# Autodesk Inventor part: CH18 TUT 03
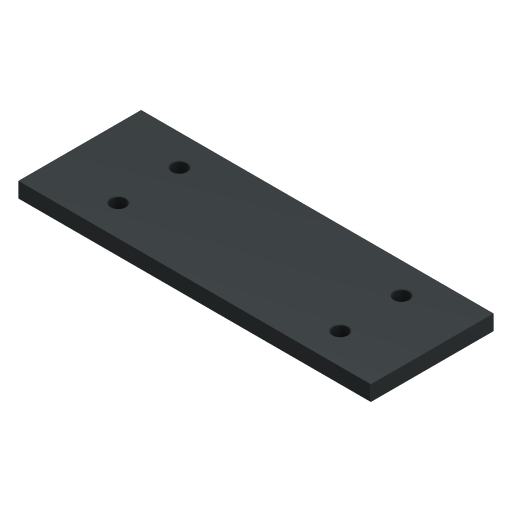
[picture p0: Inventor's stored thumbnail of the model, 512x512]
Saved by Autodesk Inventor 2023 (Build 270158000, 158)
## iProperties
Created: 2016-05
Part Number: CH18 TUT 03
Material: Iron, Cast
Document SubType Name: Modeling
Designer: CADCIM
Density: 7.15 g/cm^3
Appearance: Iron Gray
Mass: 161.642 g
Surface Area: 109.071 cm^2
Volume: 22.6073 cm^3
Author: CADCIM
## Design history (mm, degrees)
sketch "Sketch1"
  geometry: L1 (0, 40)-(115, 40); L2 (115, 40)-(115, 0); L3 (115, 0)-(0, 0); L4 (0, 0)-(0, 40); C1 r 2.5 at (22.5, 30); C2 r 2.5 at (95, 30); C3 r 2.5 at (22.5, 10); C4 r 2.5 at (95, 10); 1 further point
  constraints: 8 end point, 4 centre point, 2 horizontal, 2 parallel, 1 coincident, 1 perpendicular, 1 vertical, 6 other
  dimensions: "d0" = 115 distance of L1.start L1.end; "d1" = 40 distance of L1.end L2.end; "d2" = 10 distance from line of L1 C1.centre; "d3" = 22.5 distance from line of L4 C1.centre; "d6" = 72.5 distance of C1.centre C2.centre; "d9" = 20 distance of C1.centre C3.centre; "d14" = 5 diameter of C2
extrude "Extrusion1" new body sketch "Sketch1" distance "d12" = 5; taper "d13" = 0 deg
body "Solid1"
